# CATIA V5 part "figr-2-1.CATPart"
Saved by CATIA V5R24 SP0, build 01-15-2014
Part number: figr-2-1
Bounding box of the stored display mesh (mm): x 0 to 10, y -99.811 to 99.811, z -49.833 to 49.833
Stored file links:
  D:\KAVITA\CATIA V5-6R2014 Project_ Kavita\CATIA V5-6R2014_partfiles\Partfiles\c02_catia_v5-6r2014_prt\figr-2-1.CATPart
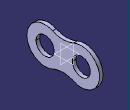
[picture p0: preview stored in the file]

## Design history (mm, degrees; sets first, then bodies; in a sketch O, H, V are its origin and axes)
Body1 (main body)
  Sketch1 on yz-plane, origin (0, 0, 0), H (0, 1, 0), V (0, 0, 1)
    arc A1 centre (50, 0) radius 50 from (29.1667, -45.453) to (29.1666, 45.4529) ccw
    point P1 (50, 0)
    arc A2 centre (-50, 0) radius 50 from (-29.1666, 45.4529) to (-29.1667, -45.453) ccw
    point P2 (-50, 0)
    arc A3 centre (0, 109.0871) radius 70 from (-29.1666, 45.4529) to (29.1667, 45.453) ccw
    point P4 (-29.1666, 45.4529)
    point P5 (0, 39.0871)
    point P6 (29.1667, 45.453)
    point P7 (29.1667, -45.453)
    point P8 (-29.1666, -45.4529)
    arc A4 centre (0, -109.0871) radius 70 from (-29.1666, -45.4529) to (29.1667, -45.453) cw
    point P10 (-29.1667, -45.453)
    point P11 (-29.1666, 45.4529)
    point P12 (29.1666, 45.4529)
    point P13 (29.1667, -45.453)
    circle A5 centre (50, 0) radius 25
    circle A6 centre (-50, 0) radius 25
    distance P1 P2 = 100
    radius A1 = 50
    radius A2 = 50
    distance O P2 = 50
    radius A5 = 25
    radius A6 = 25
    radius A3 = 70
    coincidence: P1 H, P2 H, P4 A2, A3 P5, P5 V, P6 A1, A4 P10, A3 P11, A3 P12, A4 P13
    tangency: A3 A1, A3 A2
    symmetry: P6 P7 H, P4 P8 H, A3 A4 H
  Pad1: profile Sketch1, direction (1, 0, 0), length 10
